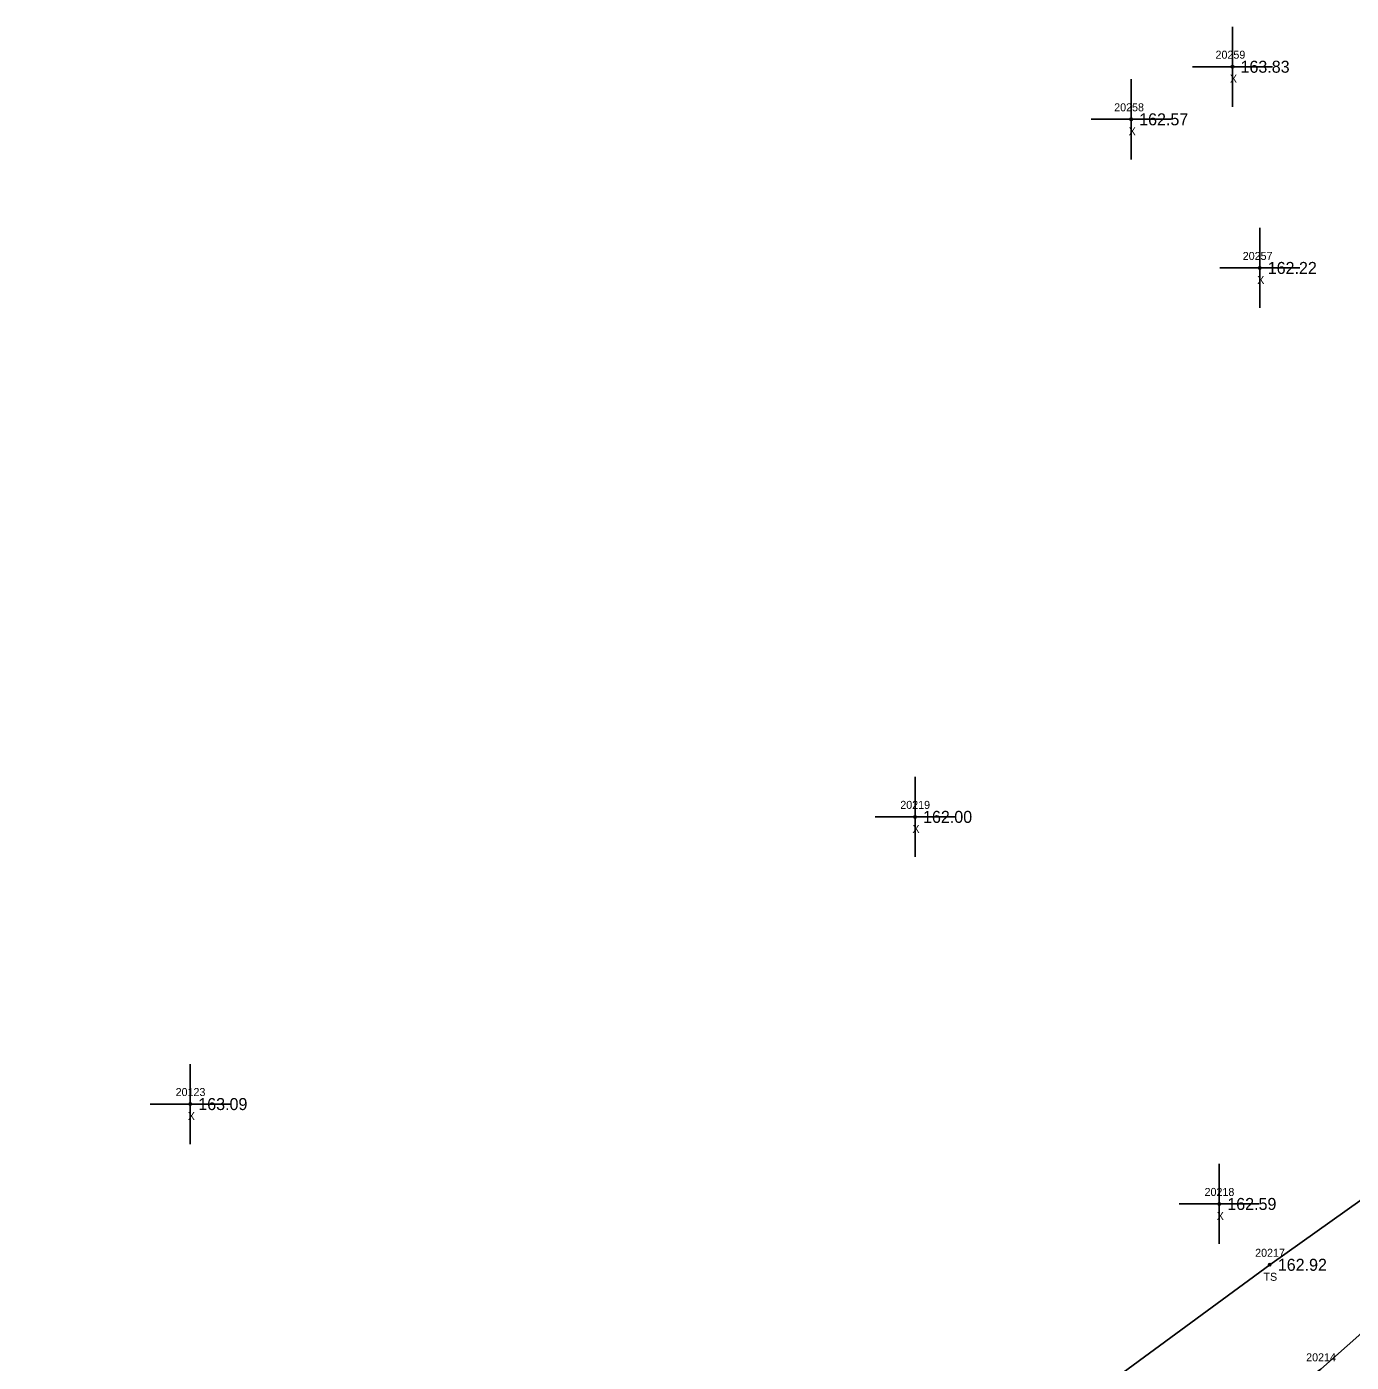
# Model space of a CAD drawing. Extents: x 2449605 to 2452431, y 1012876 to 1014922.
# Drawn here: x 2450301.6 to 2450467.1, y 1013571.4 to 1013738.3 of the extents above; entities that cross this region are included whole.
import ezdxf

# ---------------------------------------------------------------- set-up
doc = ezdxf.new("R2010")
doc.units = 0
for name, color, linetype in [('RD_DTM_BkLn1', 7, 'Continuous'), ('RD_DTM_BkLn2', 7, 'Continuous'), ('RD_DTM_BkLn_txCode', 7, 'Continuous'), ('RD_EX_Misc', 7, 'Continuous'), ('RD_EX_Misc_txCode', 7, 'Continuous'), ('RD_EX_TX_Misc_ELEV', 7, 'Continuous'), ('RD_SMD_Locator', 7, 'Continuous')]:
    doc.layers.add(name, color=color, linetype=linetype)

msp = doc.modelspace()

# ---------------------------------------------------------------- linework, layer by layer
at = {"layer": 'RD_DTM_BkLn1'}
msp.add_lwpolyline([(2450327.03, 1013465.64), (2450385.25, 1013515.48), (2450463.3, 1013570.54), (2450494.41, 1013598.14), (2450510.44, 1013608.45), (2450522.79, 1013616.8), (2450540.89, 1013630.45), (2450554.77, 1013641.65), (2450558.87, 1013649.29), (2450554.61, 1013662.77), (2450554.85, 1013667.72), (2450553.11, 1013671.81), (2450543.9, 1013678.22), (2450519.79, 1013695.83), (2450496.34, 1013716.91)], dxfattribs=at)
at = {"layer": 'RD_DTM_BkLn2'}
msp.add_lwpolyline([(2450301.63, 1013463.11), (2450375.81, 1013524.05), (2450456.92, 1013583.6), (2450494.97, 1013610.67), (2450491.89, 1013618.21), (2450482.67, 1013624.66), (2450481.76, 1013627.8), (2450488.9, 1013631.4), (2450492.06, 1013631.7), (2450504.7, 1013625.87), (2450511.15, 1013621.59), (2450516.87, 1013625.3), (2450533.14, 1013639.8), (2450547.95, 1013650.98), (2450547.85, 1013655.2), (2450545.34, 1013659.85), (2450542.55, 1013665.51), (2450510.99, 1013691), (2450491.93, 1013709.82)], dxfattribs=at)
at = {"layer": 'RD_EX_Misc'}
for p, q in [((2450452.26, 1013728.28), (2450452.26, 1013738.28)), ((2450447.26, 1013733.28), (2450457.26, 1013733.28)), ((2450439.6, 1013721.71), (2450439.6, 1013731.71)), ((2450434.6, 1013726.71), (2450444.6, 1013726.71)), ((2450455.66, 1013703.14), (2450455.66, 1013713.14)), ((2450450.66, 1013708.14), (2450460.66, 1013708.14)), ((2450412.6, 1013634.56), (2450412.6, 1013644.56)), ((2450407.6, 1013639.56), (2450417.6, 1013639.56)), ((2450322.06, 1013598.68), (2450322.06, 1013608.68)), ((2450317.06, 1013603.68), (2450327.06, 1013603.68)), ((2450450.61, 1013586.2), (2450450.61, 1013596.2)), ((2450445.61, 1013591.2), (2450455.61, 1013591.2))]:
    msp.add_line(p, q, dxfattribs=at)
at = {"layer": 'RD_SMD_Locator'}
for centre in [(2450452.26, 1013733.28), (2450439.6, 1013726.71), (2450455.66, 1013708.14), (2450412.6, 1013639.56), (2450322.06, 1013603.68), (2450450.61, 1013591.2), (2450456.92, 1013583.6)]:
    msp.add_circle(centre, 0.15, dxfattribs=at)

# ---------------------------------------------------------------- texts
at = {"layer": 'RD_DTM_BkLn_txCode'}
for s, p in [('20217', (2450455.09, 1013584.6)), ('TS', (2450456.13, 1013581.6)), ('20214', (2450461.46, 1013571.54))]:
    msp.add_text(s, height=1, dxfattribs=at).set_placement(p)
at = {"layer": 'RD_EX_Misc_txCode'}
for s, p in [('20259', (2450450.14, 1013734.28)), ('X', (2450451.94, 1013731.28)), ('20258', (2450437.48, 1013727.71)), ('X', (2450439.29, 1013724.71)), ('20257', (2450453.54, 1013709.14)), ('X', (2450455.35, 1013706.14)), ('20219', (2450410.76, 1013640.56)), ('X', (2450412.28, 1013637.56)), ('20123', (2450320.23, 1013604.68)), ('X', (2450321.75, 1013601.68)), ('20218', (2450448.77, 1013592.2)), ('X', (2450450.29, 1013589.2))]:
    msp.add_text(s, height=1, dxfattribs=at).set_placement(p)
at = {"layer": 'RD_EX_TX_Misc_ELEV'}
for s, p in [('163.83', (2450453.26, 1013732.53)), ('162.57', (2450440.6, 1013725.96)), ('162.22', (2450456.66, 1013707.39)), ('162.00', (2450413.6, 1013638.81)), ('163.09', (2450323.06, 1013602.93)), ('162.59', (2450451.61, 1013590.45)), ('162.92', (2450457.92, 1013582.85))]:
    msp.add_text(s, height=1.5, dxfattribs=at).set_placement(p)

doc.saveas('drawing.dxf')
